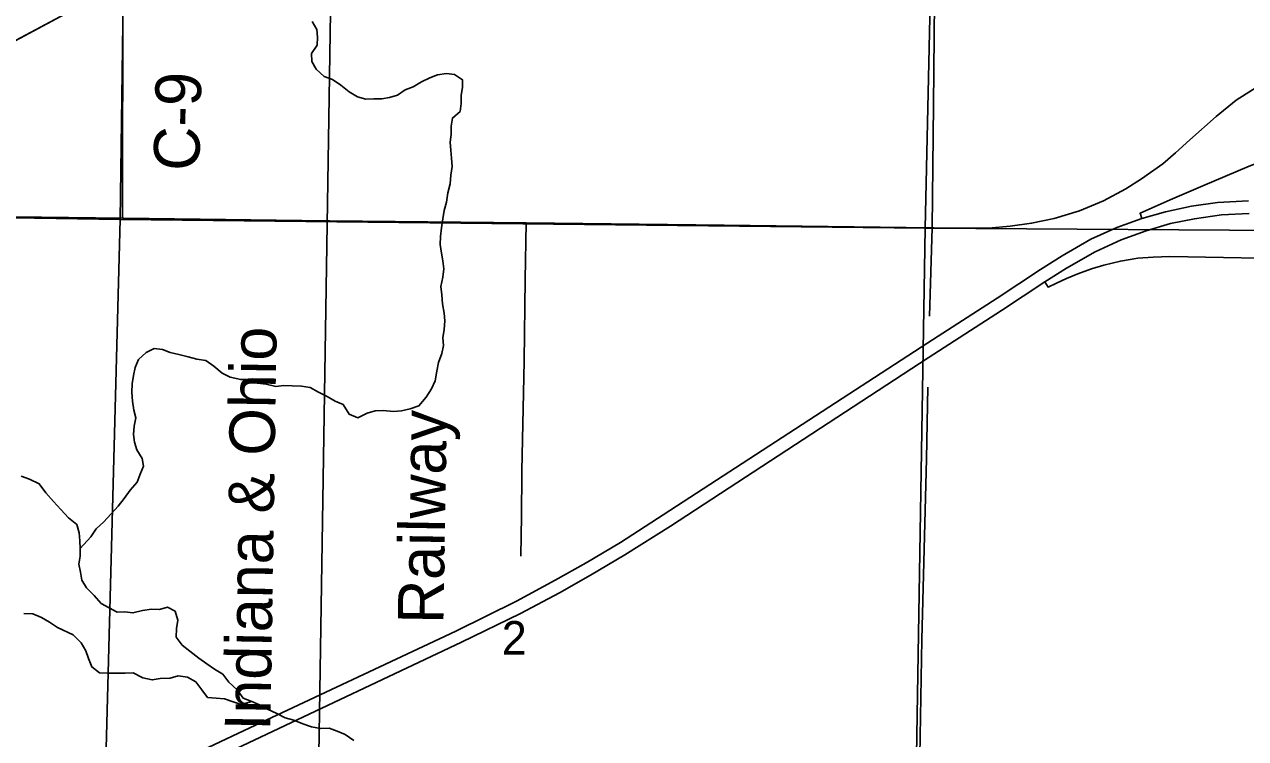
# Model space of a CAD drawing. Extents: x -6.2 to 37.4, y 0.2 to 22.2.
# Drawn here: x 5.796 to 6.554, y 19.161 to 19.604 of the extents above; entities that cross this region are included whole.
import ezdxf

# ---------------------------------------------------------------- set-up
doc = ezdxf.new("R2010")
doc.units = 0
for name, color, linetype in [('GM_X_County_Road', 7, 'Continuous'), ('GM_X_County_Road_Text', 7, 'Continuous'), ('GM_X_Interchange_Ramps', 7, 'Continuous'), ('GM_X_Minor_River', 7, 'Continuous'), ('GM_X_Rail_Line', 7, 'Continuous'), ('GM_X_Rail_Line_Text', 7, 'Continuous'), ('GM_X_Section', 7, 'Continuous'), ('GM_X_Section_Text', 7, 'Continuous'), ('GM_X_Township_Road', 7, 'Continuous'), ('GM_X_US_Route', 7, 'Continuous'), ('SH_Border', 7, 'Continuous'), ('SH_Data', 7, 'Continuous')]:
    doc.layers.add(name, color=color, linetype=linetype)

msp = doc.modelspace()

# ---------------------------------------------------------------- linework, layer by layer
at = {"layer": 'GM_X_County_Road'}
for points in [[(5.85698, 19.48401), (5.85728, 19.62878), (5.85721, 19.63789), (5.85407, 19.64343), (5.84644, 19.6534), (5.84033, 19.6643), (5.83632, 19.67612), (5.83537, 19.68941), (5.83664, 19.69889), (5.84037, 19.70851), (5.8471, 19.71525), (5.854, 19.72123), (5.85809, 19.72857), (5.85827, 19.74204), (5.86102, 19.98241)], [(6.35794, 19.42327), (6.3596, 19.47806), (6.36037, 19.55431), (6.36126, 19.63963), (6.36167, 19.67319), (6.36262, 19.74127), (6.36402, 19.85284)], [(6.3606, 19.47805), (6.38052, 19.47789), (6.3946, 19.47789), (6.40793, 19.47902), (6.42126, 19.4809), (6.43534, 19.4839), (6.45111, 19.48859), (6.46594, 19.49479), (6.47983, 19.5023), (6.4896, 19.5085), (6.50274, 19.5177), (6.51062, 19.52445), (6.51945, 19.53253), (6.53578, 19.54717), (6.54836, 19.55712), (6.56225, 19.56613), (6.57577, 19.57289), (6.59041, 19.57909), (6.6013, 19.58341), (6.60656, 19.58472), (6.61139, 19.58519)], [(5.35608, 19.48995), (5.47428, 19.4884), (5.65597, 19.48654), (5.85698, 19.48401), (5.85798, 19.48399)], [(5.85798, 19.48399), (5.98419, 19.48241), (5.9858, 19.48239), (6.10762, 19.48113), (6.23055, 19.4796), (6.3596, 19.47806), (6.3606, 19.47805)], [(6.348, 18.96099), (6.34888, 18.97097), (6.35327, 19.22276), (6.35601, 19.33473), (6.35686, 19.37932)]]:
    msp.add_lwpolyline(points, dxfattribs=at)
at = {"layer": 'GM_X_Interchange_Ramps'}
for points in [[(6.61021, 19.52311), (6.60871, 19.52318), (6.60721, 19.52325), (6.58625, 19.52316), (6.57984, 19.52259), (6.57323, 19.52156), (6.567, 19.52005), (6.56171, 19.51835), (6.55633, 19.51636), (6.52754, 19.50409), (6.50734, 19.49541), (6.48865, 19.48704), (6.48972, 19.48392)], [(6.42958, 19.44451), (6.4315, 19.44131), (6.43674, 19.44374), (6.443, 19.44668), (6.45002, 19.44961), (6.45858, 19.45268), (6.46612, 19.45485), (6.47646, 19.45741), (6.48719, 19.4592), (6.49665, 19.45983), (6.50712, 19.46022), (6.59577, 19.45868), (6.60714, 19.45843), (6.60918, 19.45838)]]:
    msp.add_lwpolyline(points, dxfattribs=at)
at = {"layer": 'GM_X_Minor_River'}
for points in [[(6.03744, 19.56555), (6.03247, 19.56357), (6.02767, 19.56025), (6.02272, 19.55883), (6.01797, 19.55798), (6.01305, 19.55808), (6.00813, 19.5578), (6.00286, 19.55923), (5.99781, 19.56237), (5.9926, 19.56645), (5.98737, 19.56997), (5.9823, 19.57197), (5.97729, 19.57643), (5.97455, 19.58123), (5.97428, 19.58617), (5.97779, 19.5914), (5.97808, 19.59633), (5.97762, 19.60108), (5.97488, 19.60607)], [(5.83081, 19.27915), (5.8374, 19.28641), (5.84072, 19.29147), (5.84554, 19.29573), (5.85445, 19.30541), (5.85815, 19.31027), (5.86185, 19.31532), (5.86612, 19.32035), (5.86793, 19.32525), (5.87011, 19.33014), (5.86927, 19.33508), (5.86597, 19.34027), (5.86456, 19.34504), (5.8639, 19.3498), (5.86439, 19.3551), (5.86525, 19.3602), (5.86403, 19.36497), (5.8632, 19.37049), (5.86275, 19.37618), (5.86305, 19.3813), (5.86391, 19.3864), (5.86496, 19.3915), (5.86696, 19.39639), (5.87178, 19.40066), (5.87675, 19.40321), (5.88185, 19.40254), (5.88673, 19.40074), (5.89201, 19.39949), (5.89784, 19.39805), (5.90311, 19.39662), (5.90877, 19.39574), (5.91381, 19.39223), (5.91883, 19.38795), (5.92389, 19.38539), (5.93048, 19.38393), (5.9354, 19.38402), (5.94084, 19.38163), (5.94613, 19.38115), (5.95216, 19.3797), (5.95709, 19.38036), (5.96238, 19.38006), (5.96806, 19.37976), (5.97353, 19.37908), (5.97877, 19.37613), (5.98401, 19.37337), (5.98906, 19.37061), (5.99394, 19.36843), (5.99779, 19.36247), (6.00304, 19.36028), (6.00897, 19.36301), (6.01392, 19.36461), (6.01884, 19.36471), (6.02527, 19.3642), (6.03019, 19.36448), (6.03552, 19.3657), (6.04105, 19.36767), (6.04552, 19.37308), (6.04884, 19.37814), (6.05122, 19.38321), (6.0521, 19.38907), (6.05316, 19.39455), (6.05517, 19.40001), (6.05622, 19.40511), (6.05594, 19.40986), (6.05661, 19.41497), (6.0571, 19.42027), (6.05663, 19.42502), (6.05562, 19.43092), (6.05536, 19.43642), (6.05471, 19.44156), (6.05597, 19.44741), (6.05645, 19.45252), (6.0558, 19.45747), (6.05495, 19.46223), (6.05431, 19.46774), (6.05442, 19.47267), (6.0551, 19.47796), (6.05597, 19.48363), (6.05665, 19.48874), (6.05808, 19.49402), (6.05896, 19.4997), (6.0604, 19.50536), (6.06089, 19.51066), (6.06157, 19.51614), (6.0613, 19.52127), (6.06084, 19.52621), (6.06037, 19.53096), (6.06104, 19.53607), (6.06115, 19.54099), (6.06182, 19.5461), (6.06664, 19.55018), (6.06731, 19.55509), (6.06723, 19.56022), (6.06809, 19.56513), (6.068, 19.56987), (6.06315, 19.57319), (6.05824, 19.57367), (6.05254, 19.57284), (6.04777, 19.57104), (6.04261, 19.56848), (6.03744, 19.56555)], [(6.00055, 19.16003), (5.99533, 19.16374), (5.99027, 19.16593), (5.98538, 19.16774), (5.97989, 19.16747), (5.97442, 19.16852), (5.96897, 19.17053), (5.96334, 19.17273), (5.95807, 19.17416), (5.95283, 19.17692), (5.94702, 19.17951), (5.94216, 19.18226), (5.93728, 19.18425), (5.93202, 19.18645), (5.92815, 19.19146), (5.92314, 19.1963), (5.91928, 19.20131), (5.91423, 19.20425), (5.90937, 19.20758), (5.90434, 19.21109), (5.89894, 19.21556), (5.8941, 19.21926), (5.89042, 19.22427), (5.89053, 19.22958), (5.89139, 19.23468), (5.88981, 19.24022), (5.88494, 19.24278), (5.87999, 19.24136), (5.87507, 19.24146), (5.86937, 19.24063), (5.86348, 19.23923), (5.85857, 19.23989), (5.85365, 19.2398), (5.84878, 19.24237), (5.84392, 19.24512), (5.83948, 19.24995), (5.83466, 19.25479), (5.83192, 19.25959), (5.83089, 19.26454), (5.83004, 19.26949), (5.83071, 19.27441), (5.83081, 19.27915), (5.83053, 19.28389), (5.83026, 19.28883), (5.82866, 19.29398), (5.82364, 19.29826), (5.81883, 19.30329), (5.8142, 19.30831), (5.80939, 19.31372), (5.80535, 19.3193), (5.79935, 19.32226), (5.79409, 19.32408)], [(5.93728, 19.18425), (5.9308, 19.18249), (5.92573, 19.18411), (5.92047, 19.18592), (5.91518, 19.18641), (5.90988, 19.1867), (5.9062, 19.19152), (5.90252, 19.19652), (5.89747, 19.19947), (5.89162, 19.20016), (5.88667, 19.19874), (5.88042, 19.19848), (5.87548, 19.19764), (5.86964, 19.19889), (5.86365, 19.20205), (5.85872, 19.20195), (5.8538, 19.20186), (5.84774, 19.2018), (5.84283, 19.20208), (5.83798, 19.20579), (5.83601, 19.21095), (5.83422, 19.21573), (5.83148, 19.22071), (5.82648, 19.22574), (5.81673, 19.23011), (5.81169, 19.23344), (5.80683, 19.23638), (5.80138, 19.23858), (5.7959, 19.23888)]]:
    msp.add_lwpolyline(points, dxfattribs=at)
at = {"layer": 'GM_X_Rail_Line'}
msp.add_lwpolyline([(5.95421, 17.70742), (5.95464, 17.73589), (5.95897, 17.99343), (5.96235, 18.24518), (5.97247, 18.73855), (5.97681, 19.01971), (5.98659, 19.63824), (5.98805, 19.72376), (5.99343, 19.98571), (6.00043, 20.49066), (6.01007, 20.99513), (6.012, 21.10742)], dxfattribs=at)
at = {"layer": 'GM_X_Section'}
for points in [[(5.86238, 19.98478), (5.85557, 19.48318), (5.35117, 19.49098), (5.36225, 19.98815)], [(6.36649, 19.98171), (6.35528, 19.47792), (5.85557, 19.48318), (5.86238, 19.98478)], [(6.36649, 19.98171), (6.86829, 19.98023), (6.85879, 19.4746), (6.35528, 19.47792)], [(5.35117, 19.49098), (5.85557, 19.48318), (5.84236, 18.9834), (5.33791, 18.98836)], [(5.85557, 19.48318), (6.35528, 19.47792), (6.34692, 18.97447), (5.84236, 18.9834)], [(6.35528, 19.47792), (6.85879, 19.4746), (6.84574, 18.97965), (6.34692, 18.97447)]]:
    msp.add_lwpolyline(points, close=True, dxfattribs=at)
at = {"layer": 'GM_X_Township_Road'}
for p, q in [((6.10708, 19.44591), (6.10762, 19.48113)), ((6.10435, 19.27442), (6.10465, 19.29941))]:
    msp.add_line(p, q, dxfattribs=at)
for points in [[(6.10609, 19.38547), (6.1063, 19.39559), (6.10708, 19.44591)], [(6.10486, 19.32474), (6.10488, 19.32727), (6.10609, 19.38547)], [(6.10465, 19.29941), (6.10466, 19.30041), (6.10486, 19.32474)]]:
    msp.add_lwpolyline(points, dxfattribs=at)
at = {"layer": 'GM_X_US_Route'}
for points in [[(5.7496, 19.08003), (5.93263, 19.16633), (6.06404, 19.22791), (6.10151, 19.24661), (6.12553, 19.25944), (6.14494, 19.2703), (6.16621, 19.28291), (6.19268, 19.29996), (6.3569, 19.40669), (6.40002, 19.43446), (6.42691, 19.45224), (6.44026, 19.46067), (6.45803, 19.47098), (6.47426, 19.47833), (6.48972, 19.48392), (6.50445, 19.48803), (6.52057, 19.49154), (6.53658, 19.49374), (6.55599, 19.49483)], [(5.75226, 19.0723), (5.93529, 19.1586), (6.06744, 19.221), (6.10418, 19.23888), (6.12819, 19.25171), (6.1476, 19.26256), (6.16888, 19.27518), (6.19728, 19.29294), (6.35706, 19.39734), (6.40268, 19.42673), (6.42958, 19.44451), (6.44293, 19.45294), (6.4607, 19.46325), (6.47693, 19.4706), (6.49239, 19.47619), (6.50741, 19.48069), (6.52233, 19.48365), (6.53921, 19.48606), (6.55632, 19.48683)]]:
    msp.add_lwpolyline(points, dxfattribs=at)
at = {"layer": 'SH_Border'}
msp.add_line((9.08657, 21.35383), (2.48033, 17.82715), dxfattribs=at)
at = {"layer": 'SH_Data'}
msp.add_lwpolyline([(9.08657, 21.35383), (2.48033, 17.82715), (9.08657, 21.53204)], close=True, dxfattribs=at)

# ---------------------------------------------------------------- texts
at = {"layer": 'GM_X_County_Road_Text'}
msp.add_text('C-9', height=0.028409, rotation=88.62591, dxfattribs=at).set_placement((5.90466, 19.51313))
at = {"layer": 'GM_X_Rail_Line_Text'}
for s, height, rotation, p in [('Indiana & Ohio', 0.0283144, 89.09601, (5.94881, 19.16605)), ('Railway', 0.028314, 89.07088, (6.05621, 19.23225))]:
    msp.add_text(s, height=height, rotation=rotation, dxfattribs=at).set_placement(p)
at = {"layer": 'GM_X_Section_Text'}
msp.add_text('2', height=0.02093, rotation=0.00001, dxfattribs=at).set_placement((6.0924, 19.21325))

doc.saveas('drawing.dxf')
